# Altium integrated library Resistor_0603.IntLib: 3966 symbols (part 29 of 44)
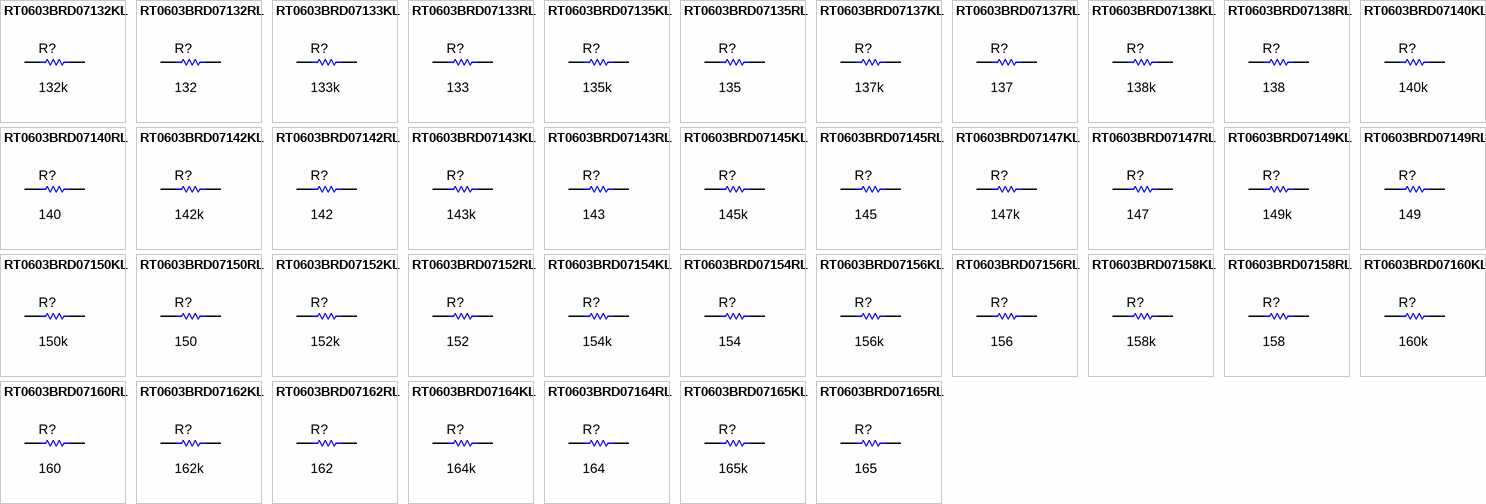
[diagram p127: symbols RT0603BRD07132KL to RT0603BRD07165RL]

## RT0603BRD07154RL
designator R?  ValueDisplayed: 154  (hidden comment: RT0603BRD07154RL)
RES, 154, 0.1%, 0.1 W, 0603; Manufacturer: Yageo America; CompType: Resistor; Value: 154; Value_Code: 154R; Tolerance_%: 0.1; Value2: 0.1W; VDC_V: 75; TempCo: 25 ppm/C; SizeArea_mm2: 1.28; SizeX_mm: 1.6; SizeY_mm: 0.8; SizeZ_mm: 1; EIA_Code: E192; U/M: EA; AEC Category: Q200
signal-integrity model Resistor
simulation model Resistor
footprint 0603
footprint 0603M
footprint 0603L
footprint 0603_HV
footprint 0603S
pins: 1, 2

## RT0603BRD07156KL
designator R?  ValueDisplayed: 156k  (hidden comment: RT0603BRD07156KL)
RES, 156 k, 0.1%, 0.1 W, 0603; Manufacturer: Yageo America; CompType: Resistor; Value: 156k; Res_ohm: 156000; Tolerance_%: 0.1; Value2: 0.1W; VDC_V: 75; TempCo: 25 ppm/C; SizeArea_mm2: 1.28; SizeX_mm: 1.6; SizeY_mm: 0.8; SizeZ_mm: 1; EIA_Code: E192; U/M: EA; AEC Category: Q200
signal-integrity model Resistor
simulation model Resistor
footprint 0603
footprint 0603M
footprint 0603L
footprint 0603_HV
footprint 0603S
pins: 1, 2

## RT0603BRD07156RL
designator R?  ValueDisplayed: 156  (hidden comment: RT0603BRD07156RL)
RES, 156, 0.1%, 0.1 W, 0603; Manufacturer: Yageo America; CompType: Resistor; Value: 156; Value_Code: 156R; Tolerance_%: 0.1; Value2: 0.1W; VDC_V: 75; TempCo: 25 ppm/C; SizeArea_mm2: 1.28; SizeX_mm: 1.6; SizeY_mm: 0.8; SizeZ_mm: 1; EIA_Code: E192; U/M: EA; AEC Category: Q200
signal-integrity model Resistor
simulation model Resistor
footprint 0603
footprint 0603M
footprint 0603L
footprint 0603_HV
footprint 0603S
pins: 1, 2

## RT0603BRD07158KL
designator R?  ValueDisplayed: 158k  (hidden comment: RT0603BRD07158KL)
RES, 158 k, 0.1%, 0.1 W, 0603; Manufacturer: Yageo America; CompType: Resistor; Value: 158k; Res_ohm: 158000; Tolerance_%: 0.1; Value2: 0.1W; VDC_V: 75; TempCo: 25 ppm/C; SizeArea_mm2: 1.28; SizeX_mm: 1.6; SizeY_mm: 0.8; SizeZ_mm: 1; EIA_Code: E192; U/M: EA; AEC Category: Q200
signal-integrity model Resistor
simulation model Resistor
footprint 0603
footprint 0603M
footprint 0603L
footprint 0603_HV
footprint 0603S
pins: 1, 2

## RT0603BRD07158RL
designator R?  ValueDisplayed: 158  (hidden comment: RT0603BRD07158RL)
RES, 158, 0.1%, 0.1 W, 0603; Manufacturer: Yageo America; CompType: Resistor; Value: 158; Value_Code: 158R; Tolerance_%: 0.1; Value2: 0.1W; VDC_V: 75; TempCo: 25 ppm/C; SizeArea_mm2: 1.28; SizeX_mm: 1.6; SizeY_mm: 0.8; SizeZ_mm: 1; EIA_Code: E192; U/M: EA; AEC Category: Q200
signal-integrity model Resistor
simulation model Resistor
footprint 0603
footprint 0603M
footprint 0603L
footprint 0603_HV
footprint 0603S
pins: 1, 2

## RT0603BRD07160KL
designator R?  ValueDisplayed: 160k  (hidden comment: RT0603BRD07160KL)
RES, 160 k, 0.1%, 0.1 W, 0603; Manufacturer: Yageo America; CompType: Resistor; Value: 160k; Res_ohm: 160000; Tolerance_%: 0.1; Value2: 0.1W; VDC_V: 75; TempCo: 25 ppm/C; SizeArea_mm2: 1.28; SizeX_mm: 1.6; SizeY_mm: 0.8; SizeZ_mm: 1; EIA_Code: E192; U/M: EA; AEC Category: Q200
signal-integrity model Resistor
simulation model Resistor
footprint 0603
footprint 0603M
footprint 0603L
footprint 0603_HV
footprint 0603S
pins: 1, 2

## RT0603BRD07160RL
designator R?  ValueDisplayed: 160  (hidden comment: RT0603BRD07160RL)
RES, 160, 0.1%, 0.1 W, 0603; Manufacturer: Yageo America; CompType: Resistor; Value: 160; Value_Code: 160R; Tolerance_%: 0.1; Value2: 0.1W; VDC_V: 75; TempCo: 25 ppm/C; SizeArea_mm2: 1.28; SizeX_mm: 1.6; SizeY_mm: 0.8; SizeZ_mm: 1; EIA_Code: E192; U/M: EA; AEC Category: Q200
signal-integrity model Resistor
simulation model Resistor
footprint 0603
footprint 0603M
footprint 0603L
footprint 0603_HV
footprint 0603S
pins: 1, 2

## RT0603BRD07162KL
designator R?  ValueDisplayed: 162k  (hidden comment: RT0603BRD07162KL)
RES, 162 k, 0.1%, 0.1 W, 0603; Manufacturer: Yageo America; CompType: Resistor; Value: 162k; Res_ohm: 162000; Tolerance_%: 0.1; Value2: 0.1W; VDC_V: 75; TempCo: 25 ppm/C; SizeArea_mm2: 1.28; SizeX_mm: 1.6; SizeY_mm: 0.8; SizeZ_mm: 1; EIA_Code: E192; U/M: EA; AEC Category: Q200
signal-integrity model Resistor
simulation model Resistor
footprint 0603
footprint 0603M
footprint 0603L
footprint 0603_HV
footprint 0603S
pins: 1, 2

## RT0603BRD07162RL
designator R?  ValueDisplayed: 162  (hidden comment: RT0603BRD07162RL)
RES, 162, 0.1%, 0.1 W, 0603; Manufacturer: Yageo America; CompType: Resistor; Value: 162; Value_Code: 162R; Tolerance_%: 0.1; Value2: 0.1W; VDC_V: 75; TempCo: 25 ppm/C; SizeArea_mm2: 1.28; SizeX_mm: 1.6; SizeY_mm: 0.8; SizeZ_mm: 1; EIA_Code: E192; U/M: EA; AEC Category: Q200
signal-integrity model Resistor
simulation model Resistor
footprint 0603
footprint 0603M
footprint 0603L
footprint 0603_HV
footprint 0603S
pins: 1, 2

## RT0603BRD07164KL
designator R?  ValueDisplayed: 164k  (hidden comment: RT0603BRD07164KL)
RES, 164 k, 0.1%, 0.1 W, 0603; Manufacturer: Yageo America; CompType: Resistor; Value: 164k; Res_ohm: 164000; Tolerance_%: 0.1; Value2: 0.1W; VDC_V: 75; TempCo: 25 ppm/C; SizeArea_mm2: 1.28; SizeX_mm: 1.6; SizeY_mm: 0.8; SizeZ_mm: 1; EIA_Code: E192; U/M: EA; AEC Category: Q200
signal-integrity model Resistor
simulation model Resistor
footprint 0603
footprint 0603M
footprint 0603L
footprint 0603_HV
footprint 0603S
pins: 1, 2

## RT0603BRD07164RL
designator R?  ValueDisplayed: 164  (hidden comment: RT0603BRD07164RL)
RES, 164, 0.1%, 0.1 W, 0603; Manufacturer: Yageo America; CompType: Resistor; Value: 164; Value_Code: 164R; Tolerance_%: 0.1; Value2: 0.1W; VDC_V: 75; TempCo: 25 ppm/C; SizeArea_mm2: 1.28; SizeX_mm: 1.6; SizeY_mm: 0.8; SizeZ_mm: 1; EIA_Code: E192; U/M: EA; AEC Category: Q200
signal-integrity model Resistor
simulation model Resistor
footprint 0603
footprint 0603M
footprint 0603L
footprint 0603_HV
footprint 0603S
pins: 1, 2

## RT0603BRD07165KL
designator R?  ValueDisplayed: 165k  (hidden comment: RT0603BRD07165KL)
RES, 165 k, 0.1%, 0.1 W, 0603; Manufacturer: Yageo America; CompType: Resistor; Value: 165k; Res_ohm: 165000; Tolerance_%: 0.1; Value2: 0.1W; VDC_V: 75; TempCo: 25 ppm/C; SizeArea_mm2: 1.28; SizeX_mm: 1.6; SizeY_mm: 0.8; SizeZ_mm: 1; EIA_Code: E192; U/M: EA; AEC Category: Q200
signal-integrity model Resistor
simulation model Resistor
footprint 0603
footprint 0603M
footprint 0603L
footprint 0603_HV
footprint 0603S
pins: 1, 2

## RT0603BRD07165RL
designator R?  ValueDisplayed: 165  (hidden comment: RT0603BRD07165RL)
RES, 165, 0.1%, 0.1 W, 0603; Manufacturer: Yageo America; CompType: Resistor; Value: 165; Value_Code: 165R; Tolerance_%: 0.1; Value2: 0.1W; VDC_V: 75; TempCo: 25 ppm/C; SizeArea_mm2: 1.28; SizeX_mm: 1.6; SizeY_mm: 0.8; SizeZ_mm: 1; EIA_Code: E192; U/M: EA; AEC Category: Q200
signal-integrity model Resistor
simulation model Resistor
footprint 0603
footprint 0603M
footprint 0603L
footprint 0603_HV
footprint 0603S
pins: 1, 2

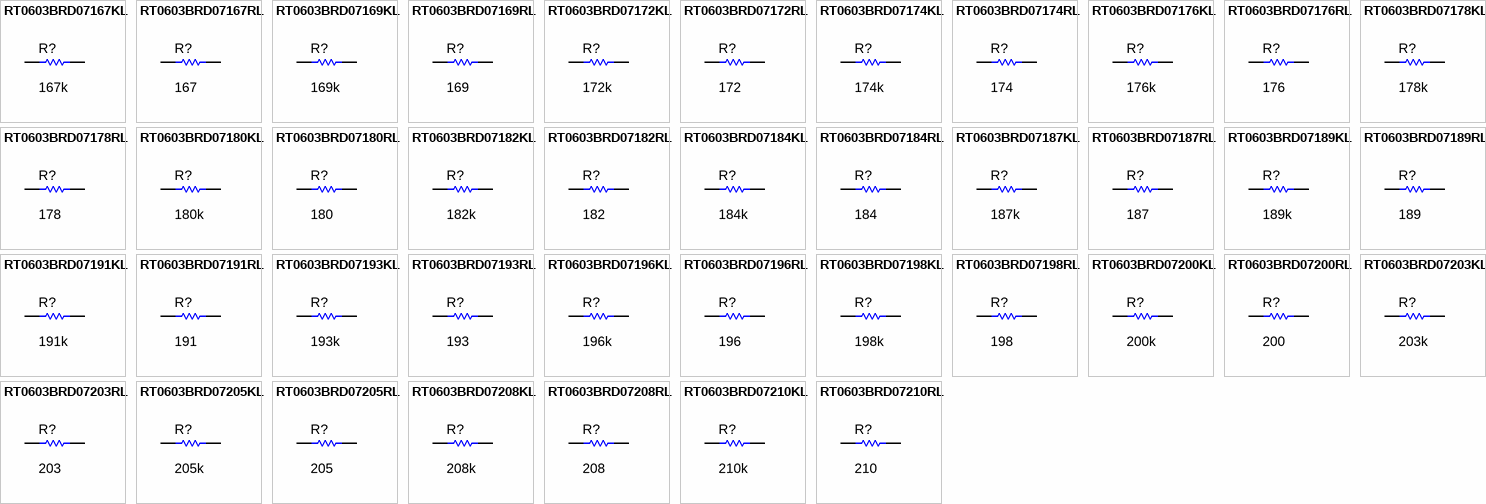
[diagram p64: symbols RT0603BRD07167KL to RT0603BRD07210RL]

## RT0603BRD07167KL
designator R?  ValueDisplayed: 167k  (hidden comment: RT0603BRD07167KL)
RES, 167 k, 0.1%, 0.1 W, 0603; Manufacturer: Yageo America; CompType: Resistor; Value: 167k; Res_ohm: 167000; Tolerance_%: 0.1; Value2: 0.1W; VDC_V: 75; TempCo: 25 ppm/C; SizeArea_mm2: 1.28; SizeX_mm: 1.6; SizeY_mm: 0.8; SizeZ_mm: 1; EIA_Code: E192; U/M: EA; AEC Category: Q200
signal-integrity model Resistor
simulation model Resistor
footprint 0603
footprint 0603M
footprint 0603L
footprint 0603_HV
footprint 0603S
pins: 1, 2

## RT0603BRD07167RL
designator R?  ValueDisplayed: 167  (hidden comment: RT0603BRD07167RL)
RES, 167, 0.1%, 0.1 W, 0603; Manufacturer: Yageo America; CompType: Resistor; Value: 167; Value_Code: 167R; Tolerance_%: 0.1; Value2: 0.1W; VDC_V: 75; TempCo: 25 ppm/C; SizeArea_mm2: 1.28; SizeX_mm: 1.6; SizeY_mm: 0.8; SizeZ_mm: 1; EIA_Code: E192; U/M: EA; AEC Category: Q200
signal-integrity model Resistor
simulation model Resistor
footprint 0603
footprint 0603M
footprint 0603L
footprint 0603_HV
footprint 0603S
pins: 1, 2

## RT0603BRD07169KL
designator R?  ValueDisplayed: 169k  (hidden comment: RT0603BRD07169KL)
RES, 169 k, 0.1%, 0.1 W, 0603; Manufacturer: Yageo America; CompType: Resistor; Value: 169k; Res_ohm: 169000; Tolerance_%: 0.1; Value2: 0.1W; VDC_V: 75; TempCo: 25 ppm/C; SizeArea_mm2: 1.28; SizeX_mm: 1.6; SizeY_mm: 0.8; SizeZ_mm: 1; EIA_Code: E192; U/M: EA; AEC Category: Q200
signal-integrity model Resistor
simulation model Resistor
footprint 0603
footprint 0603M
footprint 0603L
footprint 0603_HV
footprint 0603S
pins: 1, 2

## RT0603BRD07169RL
designator R?  ValueDisplayed: 169  (hidden comment: RT0603BRD07169RL)
RES, 169, 0.1%, 0.1 W, 0603; Manufacturer: Yageo America; CompType: Resistor; Value: 169; Value_Code: 169R; Tolerance_%: 0.1; Value2: 0.1W; VDC_V: 75; TempCo: 25 ppm/C; SizeArea_mm2: 1.28; SizeX_mm: 1.6; SizeY_mm: 0.8; SizeZ_mm: 1; EIA_Code: E192; U/M: EA; AEC Category: Q200
signal-integrity model Resistor
simulation model Resistor
footprint 0603
footprint 0603M
footprint 0603L
footprint 0603_HV
footprint 0603S
pins: 1, 2

## RT0603BRD07172KL
designator R?  ValueDisplayed: 172k  (hidden comment: RT0603BRD07172KL)
RES, 172 k, 0.1%, 0.1 W, 0603; Manufacturer: Yageo America; CompType: Resistor; Value: 172k; Res_ohm: 172000; Tolerance_%: 0.1; Value2: 0.1W; VDC_V: 75; TempCo: 25 ppm/C; SizeArea_mm2: 1.28; SizeX_mm: 1.6; SizeY_mm: 0.8; SizeZ_mm: 1; EIA_Code: E192; U/M: EA; AEC Category: Q200
signal-integrity model Resistor
simulation model Resistor
footprint 0603
footprint 0603M
footprint 0603L
footprint 0603_HV
footprint 0603S
pins: 1, 2

## RT0603BRD07172RL
designator R?  ValueDisplayed: 172  (hidden comment: RT0603BRD07172RL)
RES, 172, 0.1%, 0.1 W, 0603; Manufacturer: Yageo America; CompType: Resistor; Value: 172; Value_Code: 172R; Tolerance_%: 0.1; Value2: 0.1W; VDC_V: 75; TempCo: 25 ppm/C; SizeArea_mm2: 1.28; SizeX_mm: 1.6; SizeY_mm: 0.8; SizeZ_mm: 1; EIA_Code: E192; U/M: EA; AEC Category: Q200
signal-integrity model Resistor
simulation model Resistor
footprint 0603
footprint 0603M
footprint 0603L
footprint 0603_HV
footprint 0603S
pins: 1, 2

## RT0603BRD07174KL
designator R?  ValueDisplayed: 174k  (hidden comment: RT0603BRD07174KL)
RES, 174 k, 0.1%, 0.1 W, 0603; Manufacturer: Yageo America; CompType: Resistor; Value: 174k; Res_ohm: 174000; Tolerance_%: 0.1; Value2: 0.1W; VDC_V: 75; TempCo: 25 ppm/C; SizeArea_mm2: 1.28; SizeX_mm: 1.6; SizeY_mm: 0.8; SizeZ_mm: 1; EIA_Code: E192; U/M: EA; AEC Category: Q200
signal-integrity model Resistor
simulation model Resistor
footprint 0603
footprint 0603M
footprint 0603L
footprint 0603_HV
footprint 0603S
pins: 1, 2

## RT0603BRD07174RL
designator R?  ValueDisplayed: 174  (hidden comment: RT0603BRD07174RL)
RES, 174, 0.1%, 0.1 W, 0603; Manufacturer: Yageo America; CompType: Resistor; Value: 174; Value_Code: 174R; Tolerance_%: 0.1; Value2: 0.1W; VDC_V: 75; TempCo: 25 ppm/C; SizeArea_mm2: 1.28; SizeX_mm: 1.6; SizeY_mm: 0.8; SizeZ_mm: 1; EIA_Code: E192; U/M: EA; AEC Category: Q200
signal-integrity model Resistor
simulation model Resistor
footprint 0603
footprint 0603M
footprint 0603L
footprint 0603_HV
footprint 0603S
pins: 1, 2

## RT0603BRD07176KL
designator R?  ValueDisplayed: 176k  (hidden comment: RT0603BRD07176KL)
RES, 176 k, 0.1%, 0.1 W, 0603; Manufacturer: Yageo America; CompType: Resistor; Value: 176k; Res_ohm: 176000; Tolerance_%: 0.1; Value2: 0.1W; VDC_V: 75; TempCo: 25 ppm/C; SizeArea_mm2: 1.28; SizeX_mm: 1.6; SizeY_mm: 0.8; SizeZ_mm: 1; EIA_Code: E192; U/M: EA; AEC Category: Q200
signal-integrity model Resistor
simulation model Resistor
footprint 0603
footprint 0603M
footprint 0603L
footprint 0603_HV
footprint 0603S
pins: 1, 2

## RT0603BRD07176RL
designator R?  ValueDisplayed: 176  (hidden comment: RT0603BRD07176RL)
RES, 176, 0.1%, 0.1 W, 0603; Manufacturer: Yageo America; CompType: Resistor; Value: 176; Value_Code: 176R; Tolerance_%: 0.1; Value2: 0.1W; VDC_V: 75; TempCo: 25 ppm/C; SizeArea_mm2: 1.28; SizeX_mm: 1.6; SizeY_mm: 0.8; SizeZ_mm: 1; EIA_Code: E192; U/M: EA; AEC Category: Q200
signal-integrity model Resistor
simulation model Resistor
footprint 0603
footprint 0603M
footprint 0603L
footprint 0603_HV
footprint 0603S
pins: 1, 2

## RT0603BRD07178KL
designator R?  ValueDisplayed: 178k  (hidden comment: RT0603BRD07178KL)
RES, 178 k, 0.1%, 0.1 W, 0603; Manufacturer: Yageo America; CompType: Resistor; Value: 178k; Res_ohm: 178000; Tolerance_%: 0.1; Value2: 0.1W; VDC_V: 75; TempCo: 25 ppm/C; SizeArea_mm2: 1.28; SizeX_mm: 1.6; SizeY_mm: 0.8; SizeZ_mm: 1; EIA_Code: E192; U/M: EA; AEC Category: Q200
signal-integrity model Resistor
simulation model Resistor
footprint 0603
footprint 0603M
footprint 0603L
footprint 0603_HV
footprint 0603S
pins: 1, 2

## RT0603BRD07178RL
designator R?  ValueDisplayed: 178  (hidden comment: RT0603BRD07178RL)
RES, 178, 0.1%, 0.1 W, 0603; Manufacturer: Yageo America; CompType: Resistor; Value: 178; Value_Code: 178R; Tolerance_%: 0.1; Value2: 0.1W; VDC_V: 75; TempCo: 25 ppm/C; SizeArea_mm2: 1.28; SizeX_mm: 1.6; SizeY_mm: 0.8; SizeZ_mm: 1; EIA_Code: E192; U/M: EA; AEC Category: Q200
signal-integrity model Resistor
simulation model Resistor
footprint 0603
footprint 0603M
footprint 0603L
footprint 0603_HV
footprint 0603S
pins: 1, 2

## RT0603BRD07180KL
designator R?  ValueDisplayed: 180k  (hidden comment: RT0603BRD07180KL)
RES, 180 k, 0.1%, 0.1 W, 0603; Manufacturer: Yageo America; CompType: Resistor; Value: 180k; Res_ohm: 180000; Tolerance_%: 0.1; Value2: 0.1W; VDC_V: 75; TempCo: 25 ppm/C; SizeArea_mm2: 1.28; SizeX_mm: 1.6; SizeY_mm: 0.8; SizeZ_mm: 1; EIA_Code: E192; U/M: EA; AEC Category: Q200
signal-integrity model Resistor
simulation model Resistor
footprint 0603
footprint 0603M
footprint 0603L
footprint 0603_HV
footprint 0603S
pins: 1, 2

## RT0603BRD07180RL
designator R?  ValueDisplayed: 180  (hidden comment: RT0603BRD07180RL)
RES, 180, 0.1%, 0.1 W, 0603; Manufacturer: Yageo America; CompType: Resistor; Value: 180; Value_Code: 180R; Tolerance_%: 0.1; Value2: 0.1W; VDC_V: 75; TempCo: 25 ppm/C; SizeArea_mm2: 1.28; SizeX_mm: 1.6; SizeY_mm: 0.8; SizeZ_mm: 1; EIA_Code: E192; U/M: EA; AEC Category: Q200
signal-integrity model Resistor
simulation model Resistor
footprint 0603
footprint 0603M
footprint 0603L
footprint 0603_HV
footprint 0603S
pins: 1, 2

## RT0603BRD07182KL
designator R?  ValueDisplayed: 182k  (hidden comment: RT0603BRD07182KL)
RES, 182 k, 0.1%, 0.1 W, 0603; Manufacturer: Yageo America; CompType: Resistor; Value: 182k; Res_ohm: 182000; Tolerance_%: 0.1; Value2: 0.1W; VDC_V: 75; TempCo: 25 ppm/C; SizeArea_mm2: 1.28; SizeX_mm: 1.6; SizeY_mm: 0.8; SizeZ_mm: 1; EIA_Code: E192; U/M: EA; AEC Category: Q200
signal-integrity model Resistor
simulation model Resistor
footprint 0603
footprint 0603M
footprint 0603L
footprint 0603_HV
footprint 0603S
pins: 1, 2

## RT0603BRD07182RL
designator R?  ValueDisplayed: 182  (hidden comment: RT0603BRD07182RL)
RES, 182, 0.1%, 0.1 W, 0603; Manufacturer: Yageo America; CompType: Resistor; Value: 182; Value_Code: 182R; Tolerance_%: 0.1; Value2: 0.1W; VDC_V: 75; TempCo: 25 ppm/C; SizeArea_mm2: 1.28; SizeX_mm: 1.6; SizeY_mm: 0.8; SizeZ_mm: 1; EIA_Code: E192; U/M: EA; AEC Category: Q200
signal-integrity model Resistor
simulation model Resistor
footprint 0603
footprint 0603M
footprint 0603L
footprint 0603_HV
footprint 0603S
pins: 1, 2

## RT0603BRD07184KL
designator R?  ValueDisplayed: 184k  (hidden comment: RT0603BRD07184KL)
RES, 184 k, 0.1%, 0.1 W, 0603; Manufacturer: Yageo America; CompType: Resistor; Value: 184k; Res_ohm: 184000; Tolerance_%: 0.1; Value2: 0.1W; VDC_V: 75; TempCo: 25 ppm/C; SizeArea_mm2: 1.28; SizeX_mm: 1.6; SizeY_mm: 0.8; SizeZ_mm: 1; EIA_Code: E192; U/M: EA; AEC Category: Q200
signal-integrity model Resistor
simulation model Resistor
footprint 0603
footprint 0603M
footprint 0603L
footprint 0603_HV
footprint 0603S
pins: 1, 2

## RT0603BRD07184RL
designator R?  ValueDisplayed: 184  (hidden comment: RT0603BRD07184RL)
RES, 184, 0.1%, 0.1 W, 0603; Manufacturer: Yageo America; CompType: Resistor; Value: 184; Value_Code: 184R; Tolerance_%: 0.1; Value2: 0.1W; VDC_V: 75; TempCo: 25 ppm/C; SizeArea_mm2: 1.28; SizeX_mm: 1.6; SizeY_mm: 0.8; SizeZ_mm: 1; EIA_Code: E192; U/M: EA; AEC Category: Q200
signal-integrity model Resistor
simulation model Resistor
footprint 0603
footprint 0603M
footprint 0603L
footprint 0603_HV
footprint 0603S
pins: 1, 2

## RT0603BRD07187KL
designator R?  ValueDisplayed: 187k  (hidden comment: RT0603BRD07187KL)
RES, 187 k, 0.1%, 0.1 W, 0603; Manufacturer: Yageo America; CompType: Resistor; Value: 187k; Res_ohm: 187000; Tolerance_%: 0.1; Value2: 0.1W; VDC_V: 75; TempCo: 25 ppm/C; SizeArea_mm2: 1.28; SizeX_mm: 1.6; SizeY_mm: 0.8; SizeZ_mm: 1; EIA_Code: E192; U/M: EA; AEC Category: Q200
signal-integrity model Resistor
simulation model Resistor
footprint 0603
footprint 0603M
footprint 0603L
footprint 0603_HV
footprint 0603S
pins: 1, 2

## RT0603BRD07187RL
designator R?  ValueDisplayed: 187  (hidden comment: RT0603BRD07187RL)
RES, 187, 0.1%, 0.1 W, 0603; Manufacturer: Yageo America; CompType: Resistor; Value: 187; Value_Code: 187R; Tolerance_%: 0.1; Value2: 0.1W; VDC_V: 75; TempCo: 25 ppm/C; SizeArea_mm2: 1.28; SizeX_mm: 1.6; SizeY_mm: 0.8; SizeZ_mm: 1; EIA_Code: E192; U/M: EA; AEC Category: Q200
signal-integrity model Resistor
simulation model Resistor
footprint 0603
footprint 0603M
footprint 0603L
footprint 0603_HV
footprint 0603S
pins: 1, 2

## RT0603BRD07189KL
designator R?  ValueDisplayed: 189k  (hidden comment: RT0603BRD07189KL)
RES, 189 k, 0.1%, 0.1 W, 0603; Manufacturer: Yageo America; CompType: Resistor; Value: 189k; Res_ohm: 189000; Tolerance_%: 0.1; Value2: 0.1W; VDC_V: 75; TempCo: 25 ppm/C; SizeArea_mm2: 1.28; SizeX_mm: 1.6; SizeY_mm: 0.8; SizeZ_mm: 1; EIA_Code: E192; U/M: EA; AEC Category: Q200
signal-integrity model Resistor
simulation model Resistor
footprint 0603
footprint 0603M
footprint 0603L
footprint 0603_HV
footprint 0603S
pins: 1, 2

## RT0603BRD07189RL
designator R?  ValueDisplayed: 189  (hidden comment: RT0603BRD07189RL)
RES, 189, 0.1%, 0.1 W, 0603; Manufacturer: Yageo America; CompType: Resistor; Value: 189; Value_Code: 189R; Tolerance_%: 0.1; Value2: 0.1W; VDC_V: 75; TempCo: 25 ppm/C; SizeArea_mm2: 1.28; SizeX_mm: 1.6; SizeY_mm: 0.8; SizeZ_mm: 1; EIA_Code: E192; U/M: EA; AEC Category: Q200
signal-integrity model Resistor
simulation model Resistor
footprint 0603
footprint 0603M
footprint 0603L
footprint 0603_HV
footprint 0603S
pins: 1, 2

## RT0603BRD07191KL
designator R?  ValueDisplayed: 191k  (hidden comment: RT0603BRD07191KL)
RES, 191 k, 0.1%, 0.1 W, 0603; Manufacturer: Yageo America; CompType: Resistor; Value: 191k; Res_ohm: 191000; Tolerance_%: 0.1; Value2: 0.1W; VDC_V: 75; TempCo: 25 ppm/C; SizeArea_mm2: 1.28; SizeX_mm: 1.6; SizeY_mm: 0.8; SizeZ_mm: 1; EIA_Code: E192; U/M: EA; AEC Category: Q200
signal-integrity model Resistor
simulation model Resistor
footprint 0603
footprint 0603M
footprint 0603L
footprint 0603_HV
footprint 0603S
pins: 1, 2

## RT0603BRD07191RL
designator R?  ValueDisplayed: 191  (hidden comment: RT0603BRD07191RL)
RES, 191, 0.1%, 0.1 W, 0603; Manufacturer: Yageo America; CompType: Resistor; Value: 191; Value_Code: 191R; Tolerance_%: 0.1; Value2: 0.1W; VDC_V: 75; TempCo: 25 ppm/C; SizeArea_mm2: 1.28; SizeX_mm: 1.6; SizeY_mm: 0.8; SizeZ_mm: 1; EIA_Code: E192; U/M: EA; AEC Category: Q200
signal-integrity model Resistor
simulation model Resistor
footprint 0603
footprint 0603M
footprint 0603L
footprint 0603_HV
footprint 0603S
pins: 1, 2

## RT0603BRD07193KL
designator R?  ValueDisplayed: 193k  (hidden comment: RT0603BRD07193KL)
RES, 193 k, 0.1%, 0.1 W, 0603; Manufacturer: Yageo America; CompType: Resistor; Value: 193k; Res_ohm: 193000; Tolerance_%: 0.1; Value2: 0.1W; VDC_V: 75; TempCo: 25 ppm/C; SizeArea_mm2: 1.28; SizeX_mm: 1.6; SizeY_mm: 0.8; SizeZ_mm: 1; EIA_Code: E192; U/M: EA; AEC Category: Q200
signal-integrity model Resistor
simulation model Resistor
footprint 0603
footprint 0603M
footprint 0603L
footprint 0603_HV
footprint 0603S
pins: 1, 2

## RT0603BRD07193RL
designator R?  ValueDisplayed: 193  (hidden comment: RT0603BRD07193RL)
RES, 193, 0.1%, 0.1 W, 0603; Manufacturer: Yageo America; CompType: Resistor; Value: 193; Value_Code: 193R; Tolerance_%: 0.1; Value2: 0.1W; VDC_V: 75; TempCo: 25 ppm/C; SizeArea_mm2: 1.28; SizeX_mm: 1.6; SizeY_mm: 0.8; SizeZ_mm: 1; EIA_Code: E192; U/M: EA; AEC Category: Q200
signal-integrity model Resistor
simulation model Resistor
footprint 0603
footprint 0603M
footprint 0603L
footprint 0603_HV
footprint 0603S
pins: 1, 2

## RT0603BRD07196KL
designator R?  ValueDisplayed: 196k  (hidden comment: RT0603BRD07196KL)
RES, 196 k, 0.1%, 0.1 W, 0603; Manufacturer: Yageo America; CompType: Resistor; Value: 196k; Res_ohm: 196000; Tolerance_%: 0.1; Value2: 0.1W; VDC_V: 75; TempCo: 25 ppm/C; SizeArea_mm2: 1.28; SizeX_mm: 1.6; SizeY_mm: 0.8; SizeZ_mm: 1; EIA_Code: E192; U/M: EA; AEC Category: Q200
signal-integrity model Resistor
simulation model Resistor
footprint 0603
footprint 0603M
footprint 0603L
footprint 0603_HV
footprint 0603S
pins: 1, 2

## RT0603BRD07196RL
designator R?  ValueDisplayed: 196  (hidden comment: RT0603BRD07196RL)
RES, 196, 0.1%, 0.1 W, 0603; Manufacturer: Yageo America; CompType: Resistor; Value: 196; Value_Code: 196R; Tolerance_%: 0.1; Value2: 0.1W; VDC_V: 75; TempCo: 25 ppm/C; SizeArea_mm2: 1.28; SizeX_mm: 1.6; SizeY_mm: 0.8; SizeZ_mm: 1; EIA_Code: E192; U/M: EA; AEC Category: Q200
signal-integrity model Resistor
simulation model Resistor
footprint 0603
footprint 0603M
footprint 0603L
footprint 0603_HV
footprint 0603S
pins: 1, 2

## RT0603BRD07198KL
designator R?  ValueDisplayed: 198k  (hidden comment: RT0603BRD07198KL)
RES, 198 k, 0.1%, 0.1 W, 0603; Manufacturer: Yageo America; CompType: Resistor; Value: 198k; Res_ohm: 198000; Tolerance_%: 0.1; Value2: 0.1W; VDC_V: 75; TempCo: 25 ppm/C; SizeArea_mm2: 1.28; SizeX_mm: 1.6; SizeY_mm: 0.8; SizeZ_mm: 1; EIA_Code: E192; U/M: EA; AEC Category: Q200
signal-integrity model Resistor
simulation model Resistor
footprint 0603
footprint 0603M
footprint 0603L
footprint 0603_HV
footprint 0603S
pins: 1, 2

## RT0603BRD07198RL
designator R?  ValueDisplayed: 198  (hidden comment: RT0603BRD07198RL)
RES, 198, 0.1%, 0.1 W, 0603; Manufacturer: Yageo America; CompType: Resistor; Value: 198; Value_Code: 198R; Tolerance_%: 0.1; Value2: 0.1W; VDC_V: 75; TempCo: 25 ppm/C; SizeArea_mm2: 1.28; SizeX_mm: 1.6; SizeY_mm: 0.8; SizeZ_mm: 1; EIA_Code: E192; U/M: EA; AEC Category: Q200
signal-integrity model Resistor
simulation model Resistor
footprint 0603
footprint 0603M
footprint 0603L
footprint 0603_HV
footprint 0603S
pins: 1, 2

## RT0603BRD07200KL
designator R?  ValueDisplayed: 200k  (hidden comment: RT0603BRD07200KL)
RES, 200 k, 0.1%, 0.1 W, 0603; Manufacturer: Yageo America; CompType: Resistor; Value: 200k; Res_ohm: 200000; Tolerance_%: 0.1; Value2: 0.1W; VDC_V: 75; TempCo: 25 ppm/C; SizeArea_mm2: 1.28; SizeX_mm: 1.6; SizeY_mm: 0.8; SizeZ_mm: 1; EIA_Code: E192; U/M: EA; AEC Category: Q200; Green_Lifecycle: Active; Green_REACh: Passed
signal-integrity model Resistor
simulation model Resistor
footprint 0603
footprint 0603M
footprint 0603L
footprint 0603_HV
footprint 0603S
pins: 1, 2

## RT0603BRD07200RL
designator R?  ValueDisplayed: 200  (hidden comment: RT0603BRD07200RL)
RES, 200, 0.1%, 0.1 W, 0603; Manufacturer: Yageo America; CompType: Resistor; Value: 200; Value_Code: 200R; Tolerance_%: 0.1; Value2: 0.1W; VDC_V: 75; TempCo: 25 ppm/C; SizeArea_mm2: 1.28; SizeX_mm: 1.6; SizeY_mm: 0.8; SizeZ_mm: 1; EIA_Code: E192; U/M: EA; AEC Category: Q200
signal-integrity model Resistor
simulation model Resistor
footprint 0603
footprint 0603M
footprint 0603L
footprint 0603_HV
footprint 0603S
pins: 1, 2

## RT0603BRD07203KL
designator R?  ValueDisplayed: 203k  (hidden comment: RT0603BRD07203KL)
RES, 203 k, 0.1%, 0.1 W, 0603; Manufacturer: Yageo America; CompType: Resistor; Value: 203k; Res_ohm: 203000; Tolerance_%: 0.1; Value2: 0.1W; VDC_V: 75; TempCo: 25 ppm/C; SizeArea_mm2: 1.28; SizeX_mm: 1.6; SizeY_mm: 0.8; SizeZ_mm: 1; EIA_Code: E192; U/M: EA; AEC Category: Q200
signal-integrity model Resistor
simulation model Resistor
footprint 0603
footprint 0603M
footprint 0603L
footprint 0603_HV
footprint 0603S
pins: 1, 2

## RT0603BRD07203RL
designator R?  ValueDisplayed: 203  (hidden comment: RT0603BRD07203RL)
RES, 203, 0.1%, 0.1 W, 0603; Manufacturer: Yageo America; CompType: Resistor; Value: 203; Value_Code: 203R; Tolerance_%: 0.1; Value2: 0.1W; VDC_V: 75; TempCo: 25 ppm/C; SizeArea_mm2: 1.28; SizeX_mm: 1.6; SizeY_mm: 0.8; SizeZ_mm: 1; EIA_Code: E192; U/M: EA; AEC Category: Q200
signal-integrity model Resistor
simulation model Resistor
footprint 0603
footprint 0603M
footprint 0603L
footprint 0603_HV
footprint 0603S
pins: 1, 2

## RT0603BRD07205KL
designator R?  ValueDisplayed: 205k  (hidden comment: RT0603BRD07205KL)
RES, 205 k, 0.1%, 0.1 W, 0603; Manufacturer: Yageo America; CompType: Resistor; Value: 205k; Res_ohm: 205000; Tolerance_%: 0.1; Value2: 0.1W; VDC_V: 75; TempCo: 25 ppm/C; SizeArea_mm2: 1.28; SizeX_mm: 1.6; SizeY_mm: 0.8; SizeZ_mm: 1; EIA_Code: E192; U/M: EA; AEC Category: Q200
signal-integrity model Resistor
simulation model Resistor
footprint 0603
footprint 0603M
footprint 0603L
footprint 0603_HV
footprint 0603S
pins: 1, 2

## RT0603BRD07205RL
designator R?  ValueDisplayed: 205  (hidden comment: RT0603BRD07205RL)
RES, 205, 0.1%, 0.1 W, 0603; Manufacturer: Yageo America; CompType: Resistor; Value: 205; Value_Code: 205R; Tolerance_%: 0.1; Value2: 0.1W; VDC_V: 75; TempCo: 25 ppm/C; SizeArea_mm2: 1.28; SizeX_mm: 1.6; SizeY_mm: 0.8; SizeZ_mm: 1; EIA_Code: E192; U/M: EA; AEC Category: Q200
signal-integrity model Resistor
simulation model Resistor
footprint 0603
footprint 0603M
footprint 0603L
footprint 0603_HV
footprint 0603S
pins: 1, 2

## RT0603BRD07208KL
designator R?  ValueDisplayed: 208k  (hidden comment: RT0603BRD07208KL)
RES, 208 k, 0.1%, 0.1 W, 0603; Manufacturer: Yageo America; CompType: Resistor; Value: 208k; Res_ohm: 208000; Tolerance_%: 0.1; Value2: 0.1W; VDC_V: 75; TempCo: 25 ppm/C; SizeArea_mm2: 1.28; SizeX_mm: 1.6; SizeY_mm: 0.8; SizeZ_mm: 1; EIA_Code: E192; U/M: EA; AEC Category: Q200
signal-integrity model Resistor
simulation model Resistor
footprint 0603
footprint 0603M
footprint 0603L
footprint 0603_HV
footprint 0603S
pins: 1, 2

## RT0603BRD07208RL
designator R?  ValueDisplayed: 208  (hidden comment: RT0603BRD07208RL)
RES, 208, 0.1%, 0.1 W, 0603; Manufacturer: Yageo America; CompType: Resistor; Value: 208; Value_Code: 208R; Tolerance_%: 0.1; Value2: 0.1W; VDC_V: 75; TempCo: 25 ppm/C; SizeArea_mm2: 1.28; SizeX_mm: 1.6; SizeY_mm: 0.8; SizeZ_mm: 1; EIA_Code: E192; U/M: EA; AEC Category: Q200
signal-integrity model Resistor
simulation model Resistor
footprint 0603
footprint 0603M
footprint 0603L
footprint 0603_HV
footprint 0603S
pins: 1, 2

## RT0603BRD07210KL
designator R?  ValueDisplayed: 210k  (hidden comment: RT0603BRD07210KL)
RES, 210 k, 0.1%, 0.1 W, 0603; Manufacturer: Yageo America; CompType: Resistor; Value: 210k; Res_ohm: 210000; Tolerance_%: 0.1; Value2: 0.1W; VDC_V: 75; TempCo: 25 ppm/C; SizeArea_mm2: 1.28; SizeX_mm: 1.6; SizeY_mm: 0.8; SizeZ_mm: 1; EIA_Code: E192; U/M: EA; AEC Category: Q200
signal-integrity model Resistor
simulation model Resistor
footprint 0603
footprint 0603M
footprint 0603L
footprint 0603_HV
footprint 0603S
pins: 1, 2

## RT0603BRD07210RL
designator R?  ValueDisplayed: 210  (hidden comment: RT0603BRD07210RL)
RES, 210, 0.1%, 0.1 W, 0603; Manufacturer: Yageo America; CompType: Resistor; Value: 210; Value_Code: 210R; Tolerance_%: 0.1; Value2: 0.1W; VDC_V: 75; TempCo: 25 ppm/C; SizeArea_mm2: 1.28; SizeX_mm: 1.6; SizeY_mm: 0.8; SizeZ_mm: 1; EIA_Code: E192; U/M: EA; AEC Category: Q200
signal-integrity model Resistor
simulation model Resistor
footprint 0603
footprint 0603M
footprint 0603L
footprint 0603_HV
footprint 0603S
pins: 1, 2

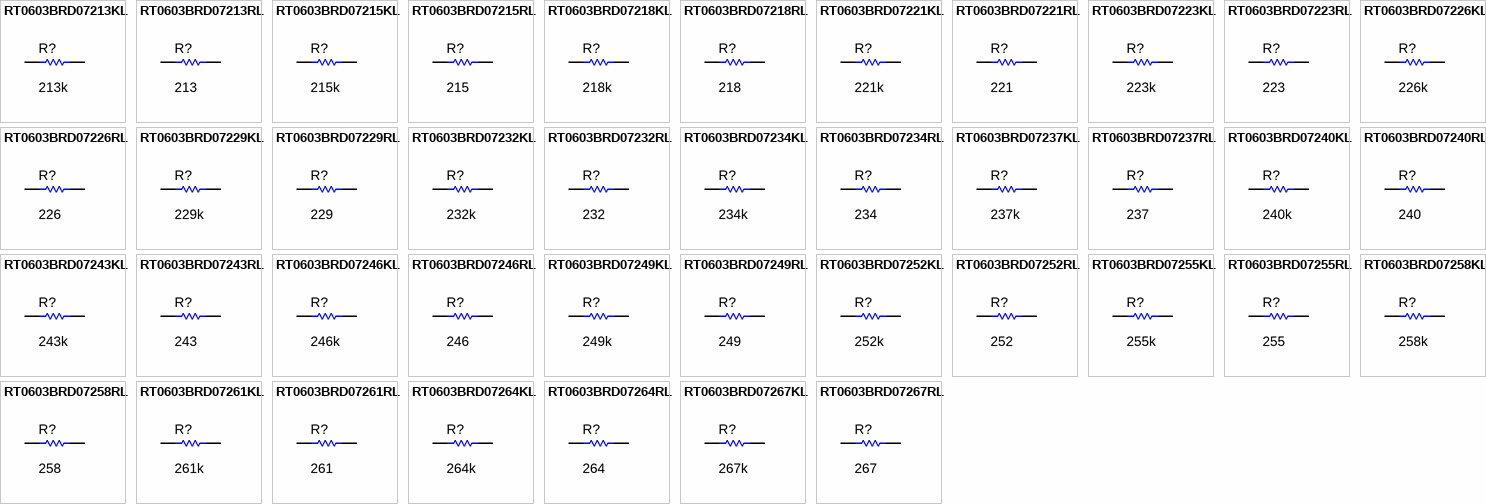
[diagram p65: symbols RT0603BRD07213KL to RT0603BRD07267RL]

## RT0603BRD07213KL
designator R?  ValueDisplayed: 213k  (hidden comment: RT0603BRD07213KL)
RES, 213 k, 0.1%, 0.1 W, 0603; Manufacturer: Yageo America; CompType: Resistor; Value: 213k; Res_ohm: 213000; Tolerance_%: 0.1; Value2: 0.1W; VDC_V: 75; TempCo: 25 ppm/C; SizeArea_mm2: 1.28; SizeX_mm: 1.6; SizeY_mm: 0.8; SizeZ_mm: 1; EIA_Code: E192; U/M: EA; AEC Category: Q200
signal-integrity model Resistor
simulation model Resistor
footprint 0603
footprint 0603M
footprint 0603L
footprint 0603_HV
footprint 0603S
pins: 1, 2

## RT0603BRD07213RL
designator R?  ValueDisplayed: 213  (hidden comment: RT0603BRD07213RL)
RES, 213, 0.1%, 0.1 W, 0603; Manufacturer: Yageo America; CompType: Resistor; Value: 213; Value_Code: 213R; Tolerance_%: 0.1; Value2: 0.1W; VDC_V: 75; TempCo: 25 ppm/C; SizeArea_mm2: 1.28; SizeX_mm: 1.6; SizeY_mm: 0.8; SizeZ_mm: 1; EIA_Code: E192; U/M: EA; AEC Category: Q200
signal-integrity model Resistor
simulation model Resistor
footprint 0603
footprint 0603M
footprint 0603L
footprint 0603_HV
footprint 0603S
pins: 1, 2

## RT0603BRD07215KL
designator R?  ValueDisplayed: 215k  (hidden comment: RT0603BRD07215KL)
RES, 215 k, 0.1%, 0.1 W, 0603; Manufacturer: Yageo America; CompType: Resistor; Value: 215k; Res_ohm: 215000; Tolerance_%: 0.1; Value2: 0.1W; VDC_V: 75; TempCo: 25 ppm/C; SizeArea_mm2: 1.28; SizeX_mm: 1.6; SizeY_mm: 0.8; SizeZ_mm: 1; EIA_Code: E192; U/M: EA; AEC Category: Q200
signal-integrity model Resistor
simulation model Resistor
footprint 0603
footprint 0603M
footprint 0603L
footprint 0603_HV
footprint 0603S
pins: 1, 2

## RT0603BRD07215RL
designator R?  ValueDisplayed: 215  (hidden comment: RT0603BRD07215RL)
RES, 215, 0.1%, 0.1 W, 0603; Manufacturer: Yageo America; CompType: Resistor; Value: 215; Value_Code: 215R; Tolerance_%: 0.1; Value2: 0.1W; VDC_V: 75; TempCo: 25 ppm/C; SizeArea_mm2: 1.28; SizeX_mm: 1.6; SizeY_mm: 0.8; SizeZ_mm: 1; EIA_Code: E192; U/M: EA; AEC Category: Q200
signal-integrity model Resistor
simulation model Resistor
footprint 0603
footprint 0603M
footprint 0603L
footprint 0603_HV
footprint 0603S
pins: 1, 2

## RT0603BRD07218KL
designator R?  ValueDisplayed: 218k  (hidden comment: RT0603BRD07218KL)
RES, 218 k, 0.1%, 0.1 W, 0603; Manufacturer: Yageo America; CompType: Resistor; Value: 218k; Res_ohm: 218000; Tolerance_%: 0.1; Value2: 0.1W; VDC_V: 75; TempCo: 25 ppm/C; SizeArea_mm2: 1.28; SizeX_mm: 1.6; SizeY_mm: 0.8; SizeZ_mm: 1; EIA_Code: E192; U/M: EA; AEC Category: Q200
signal-integrity model Resistor
simulation model Resistor
footprint 0603
footprint 0603M
footprint 0603L
footprint 0603_HV
footprint 0603S
pins: 1, 2

## RT0603BRD07218RL
designator R?  ValueDisplayed: 218  (hidden comment: RT0603BRD07218RL)
RES, 218, 0.1%, 0.1 W, 0603; Manufacturer: Yageo America; CompType: Resistor; Value: 218; Value_Code: 218R; Tolerance_%: 0.1; Value2: 0.1W; VDC_V: 75; TempCo: 25 ppm/C; SizeArea_mm2: 1.28; SizeX_mm: 1.6; SizeY_mm: 0.8; SizeZ_mm: 1; EIA_Code: E192; U/M: EA; AEC Category: Q200
signal-integrity model Resistor
simulation model Resistor
footprint 0603
footprint 0603M
footprint 0603L
footprint 0603_HV
footprint 0603S
pins: 1, 2

## RT0603BRD07221KL
designator R?  ValueDisplayed: 221k  (hidden comment: RT0603BRD07221KL)
RES, 221 k, 0.1%, 0.1 W, 0603; Manufacturer: Yageo America; CompType: Resistor; Value: 221k; Res_ohm: 221000; Tolerance_%: 0.1; Value2: 0.1W; VDC_V: 75; TempCo: 25 ppm/C; SizeArea_mm2: 1.28; SizeX_mm: 1.6; SizeY_mm: 0.8; SizeZ_mm: 1; EIA_Code: E192; U/M: EA; AEC Category: Q200
signal-integrity model Resistor
simulation model Resistor
footprint 0603
footprint 0603M
footprint 0603L
footprint 0603_HV
footprint 0603S
pins: 1, 2

## RT0603BRD07221RL
designator R?  ValueDisplayed: 221  (hidden comment: RT0603BRD07221RL)
RES, 221, 0.1%, 0.1 W, 0603; Manufacturer: Yageo America; CompType: Resistor; Value: 221; Value_Code: 221R; Tolerance_%: 0.1; Value2: 0.1W; VDC_V: 75; TempCo: 25 ppm/C; SizeArea_mm2: 1.28; SizeX_mm: 1.6; SizeY_mm: 0.8; SizeZ_mm: 1; EIA_Code: E192; U/M: EA; AEC Category: Q200
signal-integrity model Resistor
simulation model Resistor
footprint 0603
footprint 0603M
footprint 0603L
footprint 0603_HV
footprint 0603S
pins: 1, 2

## RT0603BRD07223KL
designator R?  ValueDisplayed: 223k  (hidden comment: RT0603BRD07223KL)
RES, 223 k, 0.1%, 0.1 W, 0603; Manufacturer: Yageo America; CompType: Resistor; Value: 223k; Res_ohm: 223000; Tolerance_%: 0.1; Value2: 0.1W; VDC_V: 75; TempCo: 25 ppm/C; SizeArea_mm2: 1.28; SizeX_mm: 1.6; SizeY_mm: 0.8; SizeZ_mm: 1; EIA_Code: E192; U/M: EA; AEC Category: Q200
signal-integrity model Resistor
simulation model Resistor
footprint 0603
footprint 0603M
footprint 0603L
footprint 0603_HV
footprint 0603S
pins: 1, 2

## RT0603BRD07223RL
designator R?  ValueDisplayed: 223  (hidden comment: RT0603BRD07223RL)
RES, 223, 0.1%, 0.1 W, 0603; Manufacturer: Yageo America; CompType: Resistor; Value: 223; Value_Code: 223R; Tolerance_%: 0.1; Value2: 0.1W; VDC_V: 75; TempCo: 25 ppm/C; SizeArea_mm2: 1.28; SizeX_mm: 1.6; SizeY_mm: 0.8; SizeZ_mm: 1; EIA_Code: E192; U/M: EA; AEC Category: Q200
signal-integrity model Resistor
simulation model Resistor
footprint 0603
footprint 0603M
footprint 0603L
footprint 0603_HV
footprint 0603S
pins: 1, 2

## RT0603BRD07226KL
designator R?  ValueDisplayed: 226k  (hidden comment: RT0603BRD07226KL)
RES, 226 k, 0.1%, 0.1 W, 0603; Manufacturer: Yageo America; CompType: Resistor; Value: 226k; Res_ohm: 226000; Tolerance_%: 0.1; Value2: 0.1W; VDC_V: 75; TempCo: 25 ppm/C; SizeArea_mm2: 1.28; SizeX_mm: 1.6; SizeY_mm: 0.8; SizeZ_mm: 1; EIA_Code: E192; U/M: EA; AEC Category: Q200
signal-integrity model Resistor
simulation model Resistor
footprint 0603
footprint 0603M
footprint 0603L
footprint 0603_HV
footprint 0603S
pins: 1, 2

## RT0603BRD07226RL
designator R?  ValueDisplayed: 226  (hidden comment: RT0603BRD07226RL)
RES, 226, 0.1%, 0.1 W, 0603; Manufacturer: Yageo America; CompType: Resistor; Value: 226; Value_Code: 226R; Tolerance_%: 0.1; Value2: 0.1W; VDC_V: 75; TempCo: 25 ppm/C; SizeArea_mm2: 1.28; SizeX_mm: 1.6; SizeY_mm: 0.8; SizeZ_mm: 1; EIA_Code: E192; U/M: EA; AEC Category: Q200
signal-integrity model Resistor
simulation model Resistor
footprint 0603
footprint 0603M
footprint 0603L
footprint 0603_HV
footprint 0603S
pins: 1, 2

## RT0603BRD07229KL
designator R?  ValueDisplayed: 229k  (hidden comment: RT0603BRD07229KL)
RES, 229 k, 0.1%, 0.1 W, 0603; Manufacturer: Yageo America; CompType: Resistor; Value: 229k; Res_ohm: 229000; Tolerance_%: 0.1; Value2: 0.1W; VDC_V: 75; TempCo: 25 ppm/C; SizeArea_mm2: 1.28; SizeX_mm: 1.6; SizeY_mm: 0.8; SizeZ_mm: 1; EIA_Code: E192; U/M: EA; AEC Category: Q200
signal-integrity model Resistor
simulation model Resistor
footprint 0603
footprint 0603M
footprint 0603L
footprint 0603_HV
footprint 0603S
pins: 1, 2

## RT0603BRD07229RL
designator R?  ValueDisplayed: 229  (hidden comment: RT0603BRD07229RL)
RES, 229, 0.1%, 0.1 W, 0603; Manufacturer: Yageo America; CompType: Resistor; Value: 229; Value_Code: 229R; Tolerance_%: 0.1; Value2: 0.1W; VDC_V: 75; TempCo: 25 ppm/C; SizeArea_mm2: 1.28; SizeX_mm: 1.6; SizeY_mm: 0.8; SizeZ_mm: 1; EIA_Code: E192; U/M: EA; AEC Category: Q200
signal-integrity model Resistor
simulation model Resistor
footprint 0603
footprint 0603M
footprint 0603L
footprint 0603_HV
footprint 0603S
pins: 1, 2

## RT0603BRD07232KL
designator R?  ValueDisplayed: 232k  (hidden comment: RT0603BRD07232KL)
RES, 232 k, 0.1%, 0.1 W, 0603; Manufacturer: Yageo America; CompType: Resistor; Value: 232k; Res_ohm: 232000; Tolerance_%: 0.1; Value2: 0.1W; VDC_V: 75; TempCo: 25 ppm/C; SizeArea_mm2: 1.28; SizeX_mm: 1.6; SizeY_mm: 0.8; SizeZ_mm: 1; EIA_Code: E192; U/M: EA; AEC Category: Q200
signal-integrity model Resistor
simulation model Resistor
footprint 0603
footprint 0603M
footprint 0603L
footprint 0603_HV
footprint 0603S
pins: 1, 2

## RT0603BRD07232RL
designator R?  ValueDisplayed: 232  (hidden comment: RT0603BRD07232RL)
RES, 232, 0.1%, 0.1 W, 0603; Manufacturer: Yageo America; CompType: Resistor; Value: 232; Value_Code: 232R; Tolerance_%: 0.1; Value2: 0.1W; VDC_V: 75; TempCo: 25 ppm/C; SizeArea_mm2: 1.28; SizeX_mm: 1.6; SizeY_mm: 0.8; SizeZ_mm: 1; EIA_Code: E192; U/M: EA; AEC Category: Q200
signal-integrity model Resistor
simulation model Resistor
footprint 0603
footprint 0603M
footprint 0603L
footprint 0603_HV
footprint 0603S
pins: 1, 2

## RT0603BRD07234KL
designator R?  ValueDisplayed: 234k  (hidden comment: RT0603BRD07234KL)
RES, 234 k, 0.1%, 0.1 W, 0603; Manufacturer: Yageo America; CompType: Resistor; Value: 234k; Res_ohm: 234000; Tolerance_%: 0.1; Value2: 0.1W; VDC_V: 75; TempCo: 25 ppm/C; SizeArea_mm2: 1.28; SizeX_mm: 1.6; SizeY_mm: 0.8; SizeZ_mm: 1; EIA_Code: E192; U/M: EA; AEC Category: Q200
signal-integrity model Resistor
simulation model Resistor
footprint 0603
footprint 0603M
footprint 0603L
footprint 0603_HV
footprint 0603S
pins: 1, 2

## RT0603BRD07234RL
designator R?  ValueDisplayed: 234  (hidden comment: RT0603BRD07234RL)
RES, 234, 0.1%, 0.1 W, 0603; Manufacturer: Yageo America; CompType: Resistor; Value: 234; Value_Code: 234R; Tolerance_%: 0.1; Value2: 0.1W; VDC_V: 75; TempCo: 25 ppm/C; SizeArea_mm2: 1.28; SizeX_mm: 1.6; SizeY_mm: 0.8; SizeZ_mm: 1; EIA_Code: E192; U/M: EA; AEC Category: Q200
signal-integrity model Resistor
simulation model Resistor
footprint 0603
footprint 0603M
footprint 0603L
footprint 0603_HV
footprint 0603S
pins: 1, 2

## RT0603BRD07237KL
designator R?  ValueDisplayed: 237k  (hidden comment: RT0603BRD07237KL)
RES, 237 k, 0.1%, 0.1 W, 0603; Manufacturer: Yageo America; CompType: Resistor; Value: 237k; Res_ohm: 237000; Tolerance_%: 0.1; Value2: 0.1W; VDC_V: 75; TempCo: 25 ppm/C; SizeArea_mm2: 1.28; SizeX_mm: 1.6; SizeY_mm: 0.8; SizeZ_mm: 1; EIA_Code: E192; U/M: EA; AEC Category: Q200
signal-integrity model Resistor
simulation model Resistor
footprint 0603
footprint 0603M
footprint 0603L
footprint 0603_HV
footprint 0603S
pins: 1, 2

## RT0603BRD07237RL
designator R?  ValueDisplayed: 237  (hidden comment: RT0603BRD07237RL)
RES, 237, 0.1%, 0.1 W, 0603; Manufacturer: Yageo America; CompType: Resistor; Value: 237; Value_Code: 237R; Tolerance_%: 0.1; Value2: 0.1W; VDC_V: 75; TempCo: 25 ppm/C; SizeArea_mm2: 1.28; SizeX_mm: 1.6; SizeY_mm: 0.8; SizeZ_mm: 1; EIA_Code: E192; U/M: EA; AEC Category: Q200
signal-integrity model Resistor
simulation model Resistor
footprint 0603
footprint 0603M
footprint 0603L
footprint 0603_HV
footprint 0603S
pins: 1, 2

## RT0603BRD07240KL
designator R?  ValueDisplayed: 240k  (hidden comment: RT0603BRD07240KL)
RES, 240 k, 0.1%, 0.1 W, 0603; Manufacturer: Yageo America; CompType: Resistor; Value: 240k; Res_ohm: 240000; Tolerance_%: 0.1; Value2: 0.1W; VDC_V: 75; TempCo: 25 ppm/C; SizeArea_mm2: 1.28; SizeX_mm: 1.6; SizeY_mm: 0.8; SizeZ_mm: 1; EIA_Code: E192; U/M: EA; AEC Category: Q200
signal-integrity model Resistor
simulation model Resistor
footprint 0603
footprint 0603M
footprint 0603L
footprint 0603_HV
footprint 0603S
pins: 1, 2

## RT0603BRD07240RL
designator R?  ValueDisplayed: 240  (hidden comment: RT0603BRD07240RL)
RES, 240, 0.1%, 0.1 W, 0603; Manufacturer: Yageo America; CompType: Resistor; Value: 240; Value_Code: 240R; Tolerance_%: 0.1; Value2: 0.1W; VDC_V: 75; TempCo: 25 ppm/C; SizeArea_mm2: 1.28; SizeX_mm: 1.6; SizeY_mm: 0.8; SizeZ_mm: 1; EIA_Code: E192; U/M: EA; AEC Category: Q200
signal-integrity model Resistor
simulation model Resistor
footprint 0603
footprint 0603M
footprint 0603L
footprint 0603_HV
footprint 0603S
pins: 1, 2

## RT0603BRD07243KL
designator R?  ValueDisplayed: 243k  (hidden comment: RT0603BRD07243KL)
RES, 243 k, 0.1%, 0.1 W, 0603; Manufacturer: Yageo America; CompType: Resistor; Value: 243k; Res_ohm: 243000; Tolerance_%: 0.1; Value2: 0.1W; VDC_V: 75; TempCo: 25 ppm/C; SizeArea_mm2: 1.28; SizeX_mm: 1.6; SizeY_mm: 0.8; SizeZ_mm: 1; EIA_Code: E192; U/M: EA; AEC Category: Q200
signal-integrity model Resistor
simulation model Resistor
footprint 0603
footprint 0603M
footprint 0603L
footprint 0603_HV
footprint 0603S
pins: 1, 2

## RT0603BRD07243RL
designator R?  ValueDisplayed: 243  (hidden comment: RT0603BRD07243RL)
RES, 243, 0.1%, 0.1 W, 0603; Manufacturer: Yageo America; CompType: Resistor; Value: 243; Value_Code: 243R; Tolerance_%: 0.1; Value2: 0.1W; VDC_V: 75; TempCo: 25 ppm/C; SizeArea_mm2: 1.28; SizeX_mm: 1.6; SizeY_mm: 0.8; SizeZ_mm: 1; EIA_Code: E192; U/M: EA; AEC Category: Q200
signal-integrity model Resistor
simulation model Resistor
footprint 0603
footprint 0603M
footprint 0603L
footprint 0603_HV
footprint 0603S
pins: 1, 2

## RT0603BRD07246KL
designator R?  ValueDisplayed: 246k  (hidden comment: RT0603BRD07246KL)
RES, 246 k, 0.1%, 0.1 W, 0603; Manufacturer: Yageo America; CompType: Resistor; Value: 246k; Res_ohm: 246000; Tolerance_%: 0.1; Value2: 0.1W; VDC_V: 75; TempCo: 25 ppm/C; SizeArea_mm2: 1.28; SizeX_mm: 1.6; SizeY_mm: 0.8; SizeZ_mm: 1; EIA_Code: E192; U/M: EA; AEC Category: Q200
signal-integrity model Resistor
simulation model Resistor
footprint 0603
footprint 0603M
footprint 0603L
footprint 0603_HV
footprint 0603S
pins: 1, 2

## RT0603BRD07246RL
designator R?  ValueDisplayed: 246  (hidden comment: RT0603BRD07246RL)
RES, 246, 0.1%, 0.1 W, 0603; Manufacturer: Yageo America; CompType: Resistor; Value: 246; Value_Code: 246R; Tolerance_%: 0.1; Value2: 0.1W; VDC_V: 75; TempCo: 25 ppm/C; SizeArea_mm2: 1.28; SizeX_mm: 1.6; SizeY_mm: 0.8; SizeZ_mm: 1; EIA_Code: E192; U/M: EA; AEC Category: Q200
signal-integrity model Resistor
simulation model Resistor
footprint 0603
footprint 0603M
footprint 0603L
footprint 0603_HV
footprint 0603S
pins: 1, 2

## RT0603BRD07249KL
designator R?  ValueDisplayed: 249k  (hidden comment: RT0603BRD07249KL)
RES, 249 k, 0.1%, 0.1 W, 0603; Manufacturer: Yageo America; CompType: Resistor; Value: 249k; Res_ohm: 249000; Tolerance_%: 0.1; Value2: 0.1W; VDC_V: 75; TempCo: 25 ppm/C; SizeArea_mm2: 1.28; SizeX_mm: 1.6; SizeY_mm: 0.8; SizeZ_mm: 1; EIA_Code: E192; U/M: EA; AEC Category: Q200
signal-integrity model Resistor
simulation model Resistor
footprint 0603
footprint 0603M
footprint 0603L
footprint 0603_HV
footprint 0603S
pins: 1, 2

## RT0603BRD07249RL
designator R?  ValueDisplayed: 249  (hidden comment: RT0603BRD07249RL)
RES, 249, 0.1%, 0.1 W, 0603; Manufacturer: Yageo America; CompType: Resistor; Value: 249; Value_Code: 249R; Tolerance_%: 0.1; Value2: 0.1W; VDC_V: 75; TempCo: 25 ppm/C; SizeArea_mm2: 1.28; SizeX_mm: 1.6; SizeY_mm: 0.8; SizeZ_mm: 1; EIA_Code: E192; U/M: EA; AEC Category: Q200
signal-integrity model Resistor
simulation model Resistor
footprint 0603
footprint 0603M
footprint 0603L
footprint 0603_HV
footprint 0603S
pins: 1, 2

## RT0603BRD07252KL
designator R?  ValueDisplayed: 252k  (hidden comment: RT0603BRD07252KL)
RES, 252 k, 0.1%, 0.1 W, 0603; Manufacturer: Yageo America; CompType: Resistor; Value: 252k; Res_ohm: 252000; Tolerance_%: 0.1; Value2: 0.1W; VDC_V: 75; TempCo: 25 ppm/C; SizeArea_mm2: 1.28; SizeX_mm: 1.6; SizeY_mm: 0.8; SizeZ_mm: 1; EIA_Code: E192; U/M: EA; AEC Category: Q200
signal-integrity model Resistor
simulation model Resistor
footprint 0603
footprint 0603M
footprint 0603L
footprint 0603_HV
footprint 0603S
pins: 1, 2

## RT0603BRD07252RL
designator R?  ValueDisplayed: 252  (hidden comment: RT0603BRD07252RL)
RES, 252, 0.1%, 0.1 W, 0603; Manufacturer: Yageo America; CompType: Resistor; Value: 252; Value_Code: 252R; Tolerance_%: 0.1; Value2: 0.1W; VDC_V: 75; TempCo: 25 ppm/C; SizeArea_mm2: 1.28; SizeX_mm: 1.6; SizeY_mm: 0.8; SizeZ_mm: 1; EIA_Code: E192; U/M: EA; AEC Category: Q200
signal-integrity model Resistor
simulation model Resistor
footprint 0603
footprint 0603M
footprint 0603L
footprint 0603_HV
footprint 0603S
pins: 1, 2

## RT0603BRD07255KL
designator R?  ValueDisplayed: 255k  (hidden comment: RT0603BRD07255KL)
RES, 255 k, 0.1%, 0.1 W, 0603; Manufacturer: Yageo America; CompType: Resistor; Value: 255k; Res_ohm: 255000; Tolerance_%: 0.1; Value2: 0.1W; VDC_V: 75; TempCo: 25 ppm/C; SizeArea_mm2: 1.28; SizeX_mm: 1.6; SizeY_mm: 0.8; SizeZ_mm: 1; EIA_Code: E192; U/M: EA; AEC Category: Q200
signal-integrity model Resistor
simulation model Resistor
footprint 0603
footprint 0603M
footprint 0603L
footprint 0603_HV
footprint 0603S
pins: 1, 2

## RT0603BRD07255RL
designator R?  ValueDisplayed: 255  (hidden comment: RT0603BRD07255RL)
RES, 255, 0.1%, 0.1 W, 0603; Manufacturer: Yageo America; CompType: Resistor; Value: 255; Value_Code: 255R; Tolerance_%: 0.1; Value2: 0.1W; VDC_V: 75; TempCo: 25 ppm/C; SizeArea_mm2: 1.28; SizeX_mm: 1.6; SizeY_mm: 0.8; SizeZ_mm: 1; EIA_Code: E192; U/M: EA; AEC Category: Q200
signal-integrity model Resistor
simulation model Resistor
footprint 0603
footprint 0603M
footprint 0603L
footprint 0603_HV
footprint 0603S
pins: 1, 2

## RT0603BRD07258KL
designator R?  ValueDisplayed: 258k  (hidden comment: RT0603BRD07258KL)
RES, 258 k, 0.1%, 0.1 W, 0603; Manufacturer: Yageo America; CompType: Resistor; Value: 258k; Res_ohm: 258000; Tolerance_%: 0.1; Value2: 0.1W; VDC_V: 75; TempCo: 25 ppm/C; SizeArea_mm2: 1.28; SizeX_mm: 1.6; SizeY_mm: 0.8; SizeZ_mm: 1; EIA_Code: E192; U/M: EA; AEC Category: Q200
signal-integrity model Resistor
simulation model Resistor
footprint 0603
footprint 0603M
footprint 0603L
footprint 0603_HV
footprint 0603S
pins: 1, 2

## RT0603BRD07258RL
designator R?  ValueDisplayed: 258  (hidden comment: RT0603BRD07258RL)
RES, 258, 0.1%, 0.1 W, 0603; Manufacturer: Yageo America; CompType: Resistor; Value: 258; Value_Code: 258R; Tolerance_%: 0.1; Value2: 0.1W; VDC_V: 75; TempCo: 25 ppm/C; SizeArea_mm2: 1.28; SizeX_mm: 1.6; SizeY_mm: 0.8; SizeZ_mm: 1; EIA_Code: E192; U/M: EA; AEC Category: Q200
signal-integrity model Resistor
simulation model Resistor
footprint 0603
footprint 0603M
footprint 0603L
footprint 0603_HV
footprint 0603S
pins: 1, 2

## RT0603BRD07261KL
designator R?  ValueDisplayed: 261k  (hidden comment: RT0603BRD07261KL)
RES, 261 k, 0.1%, 0.1 W, 0603; Manufacturer: Yageo America; CompType: Resistor; Value: 261k; Res_ohm: 261000; Tolerance_%: 0.1; Value2: 0.1W; VDC_V: 75; TempCo: 25 ppm/C; SizeArea_mm2: 1.28; SizeX_mm: 1.6; SizeY_mm: 0.8; SizeZ_mm: 1; EIA_Code: E192; U/M: EA; AEC Category: Q200
signal-integrity model Resistor
simulation model Resistor
footprint 0603
footprint 0603M
footprint 0603L
footprint 0603_HV
footprint 0603S
pins: 1, 2

## RT0603BRD07261RL
designator R?  ValueDisplayed: 261  (hidden comment: RT0603BRD07261RL)
RES, 261, 0.1%, 0.1 W, 0603; Manufacturer: Yageo America; CompType: Resistor; Value: 261; Value_Code: 261R; Tolerance_%: 0.1; Value2: 0.1W; VDC_V: 75; TempCo: 25 ppm/C; SizeArea_mm2: 1.28; SizeX_mm: 1.6; SizeY_mm: 0.8; SizeZ_mm: 1; EIA_Code: E192; U/M: EA; AEC Category: Q200
signal-integrity model Resistor
simulation model Resistor
footprint 0603
footprint 0603M
footprint 0603L
footprint 0603_HV
footprint 0603S
pins: 1, 2

## RT0603BRD07264KL
designator R?  ValueDisplayed: 264k  (hidden comment: RT0603BRD07264KL)
RES, 264 k, 0.1%, 0.1 W, 0603; Manufacturer: Yageo America; CompType: Resistor; Value: 264k; Res_ohm: 264000; Tolerance_%: 0.1; Value2: 0.1W; VDC_V: 75; TempCo: 25 ppm/C; SizeArea_mm2: 1.28; SizeX_mm: 1.6; SizeY_mm: 0.8; SizeZ_mm: 1; EIA_Code: E192; U/M: EA; AEC Category: Q200
signal-integrity model Resistor
simulation model Resistor
footprint 0603
footprint 0603M
footprint 0603L
footprint 0603_HV
footprint 0603S
pins: 1, 2

## RT0603BRD07264RL
designator R?  ValueDisplayed: 264  (hidden comment: RT0603BRD07264RL)
RES, 264, 0.1%, 0.1 W, 0603; Manufacturer: Yageo America; CompType: Resistor; Value: 264; Value_Code: 264R; Tolerance_%: 0.1; Value2: 0.1W; VDC_V: 75; TempCo: 25 ppm/C; SizeArea_mm2: 1.28; SizeX_mm: 1.6; SizeY_mm: 0.8; SizeZ_mm: 1; EIA_Code: E192; U/M: EA; AEC Category: Q200
signal-integrity model Resistor
simulation model Resistor
footprint 0603
footprint 0603M
footprint 0603L
footprint 0603_HV
footprint 0603S
pins: 1, 2

## RT0603BRD07267KL
designator R?  ValueDisplayed: 267k  (hidden comment: RT0603BRD07267KL)
RES, 267 k, 0.1%, 0.1 W, 0603; Manufacturer: Yageo America; CompType: Resistor; Value: 267k; Res_ohm: 267000; Tolerance_%: 0.1; Value2: 0.1W; VDC_V: 75; TempCo: 25 ppm/C; SizeArea_mm2: 1.28; SizeX_mm: 1.6; SizeY_mm: 0.8; SizeZ_mm: 1; EIA_Code: E192; U/M: EA; AEC Category: Q200
signal-integrity model Resistor
simulation model Resistor
footprint 0603
footprint 0603M
footprint 0603L
footprint 0603_HV
footprint 0603S
pins: 1, 2

## RT0603BRD07267RL
designator R?  ValueDisplayed: 267  (hidden comment: RT0603BRD07267RL)
RES, 267, 0.1%, 0.1 W, 0603; Manufacturer: Yageo America; CompType: Resistor; Value: 267; Value_Code: 267R; Tolerance_%: 0.1; Value2: 0.1W; VDC_V: 75; TempCo: 25 ppm/C; SizeArea_mm2: 1.28; SizeX_mm: 1.6; SizeY_mm: 0.8; SizeZ_mm: 1; EIA_Code: E192; U/M: EA; AEC Category: Q200
signal-integrity model Resistor
simulation model Resistor
footprint 0603
footprint 0603M
footprint 0603L
footprint 0603_HV
footprint 0603S
pins: 1, 2

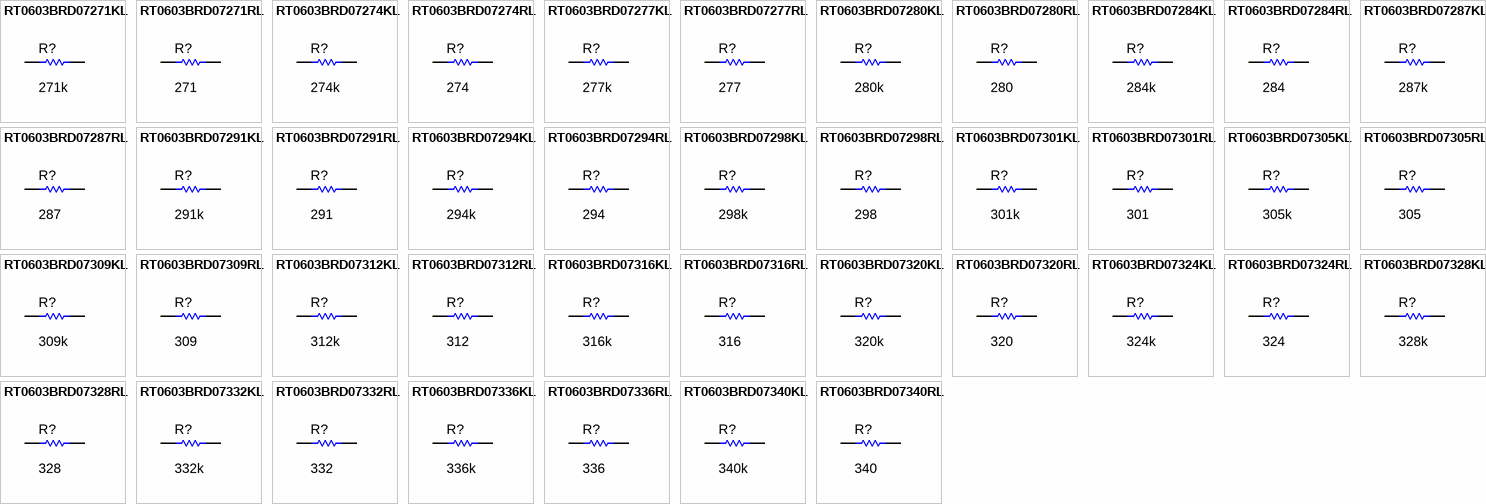
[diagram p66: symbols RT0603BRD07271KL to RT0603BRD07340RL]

## RT0603BRD07271KL
designator R?  ValueDisplayed: 271k  (hidden comment: RT0603BRD07271KL)
RES, 271 k, 0.1%, 0.1 W, 0603; Manufacturer: Yageo America; CompType: Resistor; Value: 271k; Res_ohm: 271000; Tolerance_%: 0.1; Value2: 0.1W; VDC_V: 75; TempCo: 25 ppm/C; SizeArea_mm2: 1.28; SizeX_mm: 1.6; SizeY_mm: 0.8; SizeZ_mm: 1; EIA_Code: E192; U/M: EA; AEC Category: Q200
signal-integrity model Resistor
simulation model Resistor
footprint 0603
footprint 0603M
footprint 0603L
footprint 0603_HV
footprint 0603S
pins: 1, 2

## RT0603BRD07271RL
designator R?  ValueDisplayed: 271  (hidden comment: RT0603BRD07271RL)
RES, 271, 0.1%, 0.1 W, 0603; Manufacturer: Yageo America; CompType: Resistor; Value: 271; Value_Code: 271R; Tolerance_%: 0.1; Value2: 0.1W; VDC_V: 75; TempCo: 25 ppm/C; SizeArea_mm2: 1.28; SizeX_mm: 1.6; SizeY_mm: 0.8; SizeZ_mm: 1; EIA_Code: E192; U/M: EA; AEC Category: Q200
signal-integrity model Resistor
simulation model Resistor
footprint 0603
footprint 0603M
footprint 0603L
footprint 0603_HV
footprint 0603S
pins: 1, 2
